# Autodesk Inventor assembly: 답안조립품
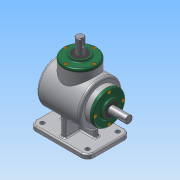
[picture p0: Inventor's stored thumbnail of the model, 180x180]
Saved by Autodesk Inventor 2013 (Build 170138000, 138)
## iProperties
Created: 2016-09
Part Number: 답안조립품
Document SubType Name: Assembly
Designer: Administrator
Author: Administrator
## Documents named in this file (14)
- C:\Users\Administrator\Desktop\460908V1005\답안조립품.iam
- C:\Users\Administrator\Desktop\460908V1005\본체.ipt
- C:\Users\Administrator\Desktop\460908V1005\베어링 6203.ipt
- C:\Users\Administrator\Desktop\460908V1005\커버.ipt
- C:\Users\Administrator\Desktop\460908V1005\오일실 17 32 8.ipt
- C:\Users\Administrator\Desktop\460908V1005\메인 축.ipt
- 메인 축.ipt
- C:\Users\Administrator\Desktop\460908V1005\서브 축.ipt
- 서브 축.ipt
- C:\Users\Administrator\Desktop\460908V1005\키 5x5.ipt
- C:\Users\Administrator\Desktop\460908V1005\키 4x4.ipt
- C:\Users\Administrator\Desktop\460908V1005\메인 베벨기어.ipt
- C:\Users\Administrator\Desktop\460908V1005\서브 베벨기어.ipt
- C:\Users\Administrator\Desktop\460908V1005\M4.ipt
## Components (8 placed, 1 different names)
1. M4:2
2. M4:3
3. M4:4
4. M4:5
5. M4:1
6. M4:6
7. M4:7
8. M4:8
